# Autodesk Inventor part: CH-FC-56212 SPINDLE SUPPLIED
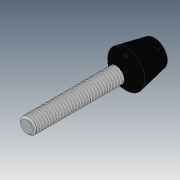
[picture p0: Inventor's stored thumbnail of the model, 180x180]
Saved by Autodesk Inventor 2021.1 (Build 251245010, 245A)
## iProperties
Created: 2020-03
Part Number: CH-FC-56212 SPINDLE SUPPLIED
Material: Ogólny
Document SubType Name: Modeling
Designer: user
Density: 1 g/cm^3
Appearance: Domyślna
Author: user
Revision Number: ÈÎºÎ
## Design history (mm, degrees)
feature "Ðý×ª2"
node "Bryła1"
